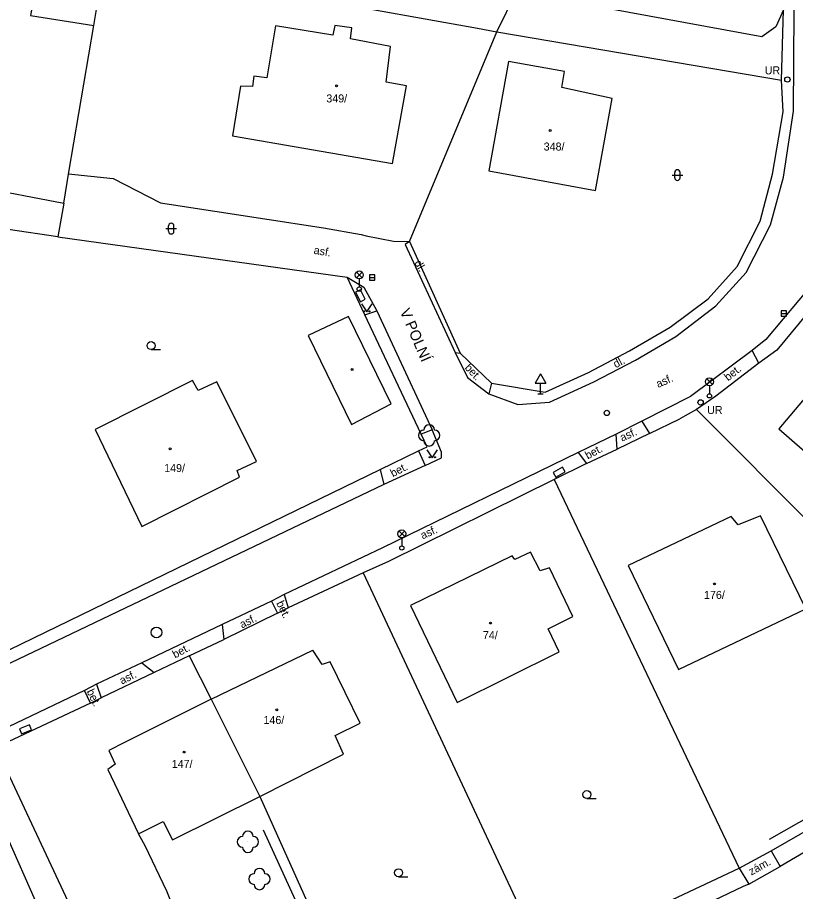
# Model space of a CAD drawing. Extents: x -737812 to -729375, y -1123000 to -1115500.
# Drawn here: x -736746 to -736673, y -1119111.9 to -1119030 of the extents above; entities that cross this region are included whole.
import ezdxf

# ---------------------------------------------------------------- set-up
doc = ezdxf.new("R2010")
doc.units = 0
for name, color, linetype in [('Doplněk polohopisu', 7, 'Continuous'), ('Doplňkové značky', 7, 'Continuous'), ('Hranice - ploty_ zdi', 7, 'Continuous'), ('Hranice parcel a úz_ celk', 7, 'Continuous'), ('Komunikace', 7, 'Continuous'), ('Názvy ulic_ silnic_ žel_', 7, 'Continuous'), ('Pomocné popisy', 7, 'Continuous'), ('Popisy povr_ zn_ inž_ sítí', 7, 'Continuous'), ('Povr_ zn_ inž_ sítí - el_', 7, 'Continuous'), ('Povr_ zn_ inž_ sítí - kan_', 7, 'Continuous'), ('Povr_ zn_ inž_ sítí - vod_', 7, 'Continuous'), ('Stavební objekty', 7, 'Continuous'), ('Zeleň', 7, 'Continuous'), ('Značky druhů budov', 7, 'Continuous'), ('Značky druhů pozemků', 7, 'Continuous'), ('Čísla popisná', 7, 'Continuous')]:
    doc.layers.add(name, color=color, linetype=linetype)

msp = doc.modelspace()

# ---------------------------------------------------------------- linework, layer by layer
at = {"layer": 'Doplněk polohopisu'}
for p, q in [((-736704.94, -1119061.39), (-736704.48, -1119061.44)), ((-736676.47, -1119062.4), (-736677.12, -1119061.2)), ((-736701.54, -1119064.26), (-736701.78, -1119065.25)), ((-736687.44, -1119067.82), (-736686.74, -1119068.98)), ((-736689.75, -1119070.44), (-736689.84, -1119069.05)), ((-736708.4, -1119070.6), (-736707.77, -1119071.98)), ((-736693.41, -1119070.77), (-736692.65, -1119071.8)), ((-736711.99, -1119072.36), (-736711.64, -1119073.76)), ((-736720.99, -1119084.08), (-736720.6, -1119085.33)), ((-736722.18, -1119084.69), (-736721.6, -1119085.82)), ((-736726.78, -1119086.89), (-736726.64, -1119088.27)), ((-736734.33, -1119090.48), (-736733.18, -1119091.39)), ((-736738.59, -1119092.47), (-736738.15, -1119093.74)), ((-736739.13, -1119094.25), (-736739.7, -1119093.05)), ((-736675.33, -1119108.09), (-736674.48, -1119109.57)), ((-736678.31, -1119109.7), (-736677.43, -1119111.21))]:
    msp.add_line(p, q, dxfattribs=at)
msp.add_lwpolyline([(-736728.21, -1119123.67), (-736727.75, -1119122.27), (-736729.05, -1119119.27), (-736731.98, -1119111.87), (-736734.02, -1119107.61), (-736734.63, -1119106.48)], dxfattribs=at)
at = {"layer": 'Doplňkové značky'}
for p, q in [((-736696.94, -1119063.394), (-736697.44, -1119064.26)), ((-736696.94, -1119063.394), (-736696.44, -1119064.26)), ((-736697.44, -1119064.26), (-736696.44, -1119064.26)), ((-736696.94, -1119065.26), (-736696.94, -1119064.26)), ((-736697.19, -1119065.26), (-736696.69, -1119065.26))]:
    msp.add_line(p, q, dxfattribs=at)
at = {"layer": 'Hranice - ploty_ zdi'}
for p, q in [((-736717.3, -1119049.7), (-736713.76, -1119050.33)), ((-736713.76, -1119050.33), (-736713.3, -1119050.46)), ((-736713.3, -1119050.46), (-736710.72, -1119050.95)), ((-736704.48, -1119061.44), (-736701.54, -1119064.26)), ((-736676.47, -1119062.4), (-736680.5, -1119065.47)), ((-736682.31, -1119066.74), (-736653.66, -1119095.54)), ((-736686.74, -1119068.98), (-736683.88, -1119067.59)), ((-736686.74, -1119068.98), (-736689.75, -1119070.44)), ((-736692.65, -1119071.8), (-736689.75, -1119070.44)), ((-736711.99, -1119072.36), (-736708.4, -1119070.6)), ((-736750.09, -1119090.85), (-736711.99, -1119072.36)), ((-736695.67, -1119073.3), (-736678.31, -1119109.7)), ((-736711.19, -1119080.96), (-736713.57, -1119082.02)), ((-736713.57, -1119082.02), (-736720.6, -1119085.33)), ((-736721.6, -1119085.82), (-736726.64, -1119088.27)), ((-736721.6, -1119085.82), (-736720.6, -1119085.33)), ((-736729.89, -1119089.81), (-736726.64, -1119088.27)), ((-736729.89, -1119089.81), (-736733.18, -1119091.39)), ((-736733.18, -1119091.39), (-736738.15, -1119093.74)), ((-736739.13, -1119094.25), (-736738.15, -1119093.74)), ((-736739.13, -1119094.25), (-736748.01, -1119098.42)), ((-736675.33, -1119108.09), (-736653.66, -1119095.54)), ((-736748.01, -1119098.42), (-736730.91, -1119134.89)), ((-736715.82, -1119121.66), (-736722.91, -1119106.16)), ((-736678.31, -1119109.7), (-736675.33, -1119108.09))]:
    msp.add_line(p, q, dxfattribs=at)
for points in [[(-736674.34, -1119035.88), (-736674.17, -1119029.27), (-736674.52, -1119013.55)], [(-736701.54, -1119064.26), (-736696.52, -1119065.09), (-736692.45, -1119063.25), (-736688.59, -1119061.23), (-736684.8, -1119059.01), (-736681.22, -1119056.35), (-736678.52, -1119053.32), (-736676.37, -1119049.09), (-736675.19, -1119044.68), (-736674.21, -1119038.83), (-736674.34, -1119035.88)], [(-736710.72, -1119050.95), (-736709.22, -1119050.99), (-736704.48, -1119061.44)], [(-736708.4, -1119070.6), (-736707.56, -1119070.24), (-736708.14, -1119069.03), (-736713.41, -1119057.85), (-736715.07, -1119054.32)], [(-736669.84, -1119055.2), (-736674.8, -1119061.16), (-736676.47, -1119062.4)], [(-736680.5, -1119065.47), (-736682.31, -1119066.74), (-736683.88, -1119067.59)], [(-736692.65, -1119071.8), (-736695.67, -1119073.3), (-736711.19, -1119080.96)], [(-736713.57, -1119082.02), (-736696.6, -1119118.31), (-736678.31, -1119109.7)], [(-736675.48, -1119106.99), (-736662.16, -1119099.43), (-736654.8, -1119095.19)]]:
    msp.add_lwpolyline(points, dxfattribs=at)
at = {"layer": 'Hranice parcel a úz_ celk'}
for points in [[(-736721.98, -1119027.65), (-736717.56, -1119028.37), (-736702.85, -1119031), (-736701.03, -1119031.35), (-736699.21, -1119027.54), (-736694.87, -1119000.96)], [(-736762.16, -1119020.65), (-736762.75, -1119023.57), (-736766.15, -1119042.71), (-736741.65, -1119047.38), (-736741.17, -1119044.5), (-736738.81, -1119030.75)], [(-736674.17, -1119029.27), (-736674.89, -1119030.86), (-736676.21, -1119031.8), (-736699.21, -1119027.54)], [(-736709.22, -1119050.99), (-736701.03, -1119031.35)], [(-736701.03, -1119031.35), (-736674.34, -1119035.88)], [(-736741.2, -1119044.64), (-736737.02, -1119045.09), (-736732.59, -1119047.35), (-736717.3, -1119049.7)], [(-736741.65, -1119047.38), (-736742.19, -1119050.56)], [(-736742.19, -1119050.56), (-736746.85, -1119049.85), (-736749.66, -1119065.55), (-736753.25, -1119085.33), (-736750.09, -1119090.85)], [(-736742.19, -1119050.56), (-736715.07, -1119054.32)], [(-736729.89, -1119089.81), (-736727.81, -1119093.86)], [(-736723.27, -1119103.01), (-736712.86, -1119126.14)]]:
    msp.add_lwpolyline(points, dxfattribs=at)
at = {"layer": 'Komunikace'}
for p, q in [((-736706.23, -1119070.74), (-736707.09, -1119068.62)), ((-736677.43, -1119111.21), (-736674.48, -1119109.57))]:
    msp.add_line(p, q, dxfattribs=at)
for points in [[(-736709.22, -1119050.99), (-736709.63, -1119051.26), (-736704.94, -1119061.39), (-736703.79, -1119063.73), (-736701.78, -1119065.25), (-736699.06, -1119066.27), (-736696.09, -1119066.04), (-736691.94, -1119064.15), (-736688.04, -1119062.12), (-736684.26, -1119059.88), (-736680.51, -1119057.01), (-736677.68, -1119053.89), (-736675.4, -1119049.41), (-736674.17, -1119044.97), (-736673.23, -1119038.76), (-736673.18, -1119029.34), (-736673.35, -1119014.3), (-736673.44, -1119007.2), (-736673.57, -1118998.78)], [(-736622.49, -1119039.69), (-736623.12, -1119051.94), (-736624.1, -1119057.97), (-736625.9, -1119062.7), (-736628.62, -1119067), (-736631.54, -1119071), (-736641.44, -1119083.19), (-736650.2, -1119093.89), (-736652.55, -1119096.41), (-736657.99, -1119099.87), (-736674.48, -1119109.57)], [(-736671.1, -1119054.56), (-736675.81, -1119060.17), (-736677.12, -1119061.2), (-736682.9, -1119065.51), (-736687.44, -1119067.82), (-736689.84, -1119069.05), (-736693.41, -1119070.77), (-736711.76, -1119079.68), (-736720.99, -1119084.08), (-736722.18, -1119084.69), (-736726.78, -1119086.89), (-736734.33, -1119090.48), (-736738.59, -1119092.47), (-736739.7, -1119093.05), (-736762.61, -1119103.99), (-736767.67, -1119106.4), (-736771.32, -1119108.21)], [(-736715.07, -1119054.32), (-736713.51, -1119055.25), (-736712.28, -1119057.48)], [(-736707.77, -1119071.98), (-736706.24, -1119071.25), (-736706.23, -1119070.74)], [(-736707.77, -1119071.98), (-736711.64, -1119073.76), (-736749.52, -1119091.84), (-736775.93, -1119104.4), (-736780.5, -1119106.57), (-736783.56, -1119108)], [(-736677.43, -1119111.21), (-736677.95, -1119111.44), (-736724.57, -1119133.68)]]:
    msp.add_lwpolyline(points, dxfattribs=at)
at = {"layer": 'Povr_ zn_ inž_ sítí - el_'}
for p, q in [((-736714.204, -1119054.378), (-736713.676, -1119053.85)), ((-736713.668, -1119054.375), (-736714.196, -1119053.846)), ((-736713.94, -1119054.49), (-736713.94, -1119055.24)), ((-736681.374, -1119064.388), (-736680.846, -1119063.86)), ((-736680.838, -1119064.385), (-736681.366, -1119063.856)), ((-736681.11, -1119064.5), (-736681.11, -1119065.25)), ((-736710.214, -1119078.648), (-736709.686, -1119078.12)), ((-736709.678, -1119078.645), (-736710.206, -1119078.116)), ((-736709.95, -1119078.76), (-736709.95, -1119079.51))]:
    msp.add_line(p, q, dxfattribs=at)
for points in [[(-736714.281, -1119055.74), (-736713.824, -1119056.629), (-736713.379, -1119056.4), (-736713.836, -1119055.511)], [(-736695.516, -1119073.061), (-736694.641, -1119072.576), (-736694.884, -1119072.139), (-736695.759, -1119072.624)], [(-736745.599, -1119097.13), (-736744.673, -1119096.753), (-736744.861, -1119096.29), (-736745.787, -1119096.667)]]:
    msp.add_lwpolyline(points, close=True, dxfattribs=at)
for centre, radius in [((-736673.801, -1119035.8), 0.25), ((-736673.801, -1119035.8), 0.0005), ((-736713.94, -1119054.115), 0.375), ((-736713.94, -1119055.44), 0.2), ((-736681.11, -1119064.125), 0.375), ((-736681.11, -1119065.45), 0.2), ((-736681.941, -1119066.06), 0.25), ((-736681.941, -1119066.06), 0.0005), ((-736709.95, -1119078.385), 0.375), ((-736709.95, -1119079.71), 0.2)]:
    msp.add_circle(centre, radius, dxfattribs=at)
at = {"layer": 'Povr_ zn_ inž_ sítí - kan_'}
for p, q in [((-736712.99, -1119054.36), (-736712.49, -1119054.36)), ((-736674.39, -1119057.74), (-736673.89, -1119057.74))]:
    msp.add_line(p, q, dxfattribs=at)
for points in [[(-736712.99, -1119054.611), (-736712.49, -1119054.611), (-736712.49, -1119054.11), (-736712.99, -1119054.11)], [(-736674.39, -1119057.991), (-736673.89, -1119057.991), (-736673.89, -1119057.49), (-736674.39, -1119057.49)]]:
    msp.add_lwpolyline(points, close=True, dxfattribs=at)
msp.add_circle((-736732.95, -1119087.62), 0.5, dxfattribs=at)
at = {"layer": 'Povr_ zn_ inž_ sítí - vod_'}
msp.add_circle((-736690.73, -1119067.05), 0.25, dxfattribs=at)
at = {"layer": 'Stavební objekty'}
for points in [[(-736743.77, -1119024.28), (-736744.76, -1119029.81), (-736738.81, -1119030.75), (-736737.91, -1119025.27)], [(-736725.84, -1119041.09), (-736710.81, -1119043.67), (-736709.52, -1119036.39), (-736711.41, -1119036.04), (-736711.02, -1119032.72), (-736714.77, -1119031.99), (-736714.64, -1119030.96), (-736716.24, -1119030.74), (-736716.41, -1119031.65), (-736721.79, -1119030.78), (-736722.61, -1119035.65), (-736723.82, -1119035.48), (-736723.95, -1119036.47), (-736725.07, -1119036.43)], [(-736699.94, -1119034.12), (-736701.78, -1119044.37), (-736691.78, -1119046.21), (-736690.22, -1119037.58), (-736694.94, -1119036.54), (-736694.71, -1119035.04)], [(-736694.71, -1119035.04), (-736699.94, -1119034.12)], [(-736725.07, -1119036.43), (-736725.84, -1119041.09)], [(-736718.72, -1119059.8), (-736714.67, -1119068.13), (-736710.94, -1119066.19), (-736714.94, -1119058.01)], [(-736714.94, -1119058.01), (-736718.72, -1119059.8)], [(-736667.26, -1119059.85), (-736674.59, -1119068.54), (-736667.07, -1119075.09), (-736659.65, -1119066.4), (-736658.3, -1119064.82), (-736664.85, -1119059.3), (-736666.1, -1119060.78)], [(-736725.39, -1119072.46), (-736723.58, -1119071.6), (-736727.3, -1119064.15), (-736729.04, -1119064.94), (-736729.56, -1119064.02), (-736738.71, -1119068.6)], [(-736738.71, -1119068.6), (-736734.34, -1119077.69), (-736725.18, -1119073.07), (-736725.39, -1119072.46)], [(-736679.06, -1119076.76), (-736688.72, -1119081.35), (-736684.02, -1119091.09), (-736672.06, -1119085.41), (-736676.33, -1119076.69), (-736678.42, -1119077.55)], [(-736678.42, -1119077.55), (-736679.06, -1119076.76)], [(-736709.13, -1119085.09), (-736704.76, -1119094.2), (-736695.19, -1119089.43), (-736696.23, -1119087.28), (-736693.93, -1119086.13), (-736696.12, -1119081.57), (-736696.98, -1119081.86), (-736697.88, -1119080.1), (-736699.34, -1119080.79), (-736699.6, -1119080.43)], [(-736699.6, -1119080.43), (-736709.13, -1119085.09)], [(-736727.81, -1119093.86), (-736723.27, -1119103.01), (-736715.41, -1119099.04), (-736716.2, -1119097.29), (-736713.87, -1119096.11), (-736716.66, -1119090.36), (-736717.41, -1119090.64), (-736718.3, -1119089.29)], [(-736727.81, -1119093.86), (-736718.3, -1119089.29)], [(-736727.81, -1119093.86), (-736735.95, -1119097.94), (-736737.41, -1119098.69), (-736736.84, -1119099.97), (-736737.52, -1119100.47), (-736734.63, -1119106.48), (-736732.34, -1119105.33), (-736731.45, -1119107.05), (-736723.27, -1119103.01)], [(-736748, -1119104.47), (-736743.27, -1119115.16), (-736750.39, -1119118.54), (-736749.63, -1119119.94), (-736755.7, -1119122.69), (-736760.61, -1119111.65), (-736756.75, -1119109.61), (-736757.22, -1119108.26), (-736755.64, -1119107.74), (-736755.29, -1119108.26), (-736753.43, -1119107.27), (-736753.72, -1119106.75)]]:
    msp.add_lwpolyline(points, dxfattribs=at)
at = {"layer": 'Zeleň'}
msp.add_lwpolyline([(-736713.41, -1119057.85), (-736712.28, -1119057.48), (-736707.09, -1119068.62), (-736708.14, -1119069.03)], dxfattribs=at)
for centre in [(-736707.39, -1119069.15), (-736724.38, -1119107.24), (-736723.3, -1119110.73)]:
    msp.add_circle(centre, 0.0005, dxfattribs=at)
for centre, start, end in [((-736707.89, -1119069.15), 89.99999, 269.99999), ((-736707.39, -1119068.65), 0, 179.99999), ((-736706.89, -1119069.15), 270, 89.99999), ((-736707.39, -1119069.65), 179.99999, 359.99999), ((-736724.38, -1119106.74), 0, 179.99999), ((-736724.88, -1119107.24), 89.99999, 269.99999), ((-736723.88, -1119107.24), 270, 89.99999), ((-736724.38, -1119107.74), 179.99999, 359.99999), ((-736723.3, -1119110.23), 0, 179.99999), ((-736723.8, -1119110.73), 89.99999, 269.99999), ((-736722.8, -1119110.73), 270, 89.99999), ((-736723.3, -1119111.23), 179.99999, 359.99999)]:
    msp.add_arc(centre, 0.5, start, end, dxfattribs=at)
at = {"layer": 'Značky druhů budov'}
for centre in [(-736716.06, -1119036.4), (-736696.04, -1119040.58), (-736714.62, -1119062.98), (-736731.67, -1119070.42), (-736680.64, -1119083.08), (-736701.64, -1119086.74), (-736721.68, -1119094.88), (-736730.36, -1119098.83)]:
    msp.add_circle(centre, 0.0875, dxfattribs=at)
at = {"layer": 'Značky druhů pozemků'}
for p, q in [((-736684.62, -1119044.76), (-736683.62, -1119044.76)), ((-736684.37, -1119045.01), (-736684.37, -1119044.51)), ((-736683.87, -1119045.01), (-736683.87, -1119044.51)), ((-736732.07, -1119049.78), (-736731.07, -1119049.78)), ((-736731.82, -1119050.03), (-736731.82, -1119049.53)), ((-736731.32, -1119050.03), (-736731.32, -1119049.53)), ((-736733.46, -1119061.115), (-736732.585, -1119061.115)), ((-736692.6, -1119103.185), (-736691.725, -1119103.185)), ((-736710.26, -1119110.515), (-736709.385, -1119110.515))]:
    msp.add_line(p, q, dxfattribs=at)
for points in [[(-736713.74, -1119056.83), (-736713.24, -1119057.58), (-736712.74, -1119056.83)], [(-736707.59, -1119070.5), (-736707.09, -1119071.25), (-736706.59, -1119070.5)]]:
    msp.add_lwpolyline(points, dxfattribs=at)
for centre, radius in [((-736713.49, -1119057.53), 0.05), ((-736712.99, -1119057.53), 0.05), ((-736733.46, -1119060.74), 0.375), ((-736707.34, -1119071.2), 0.05), ((-736706.84, -1119071.2), 0.05), ((-736692.6, -1119102.81), 0.375), ((-736710.26, -1119110.14), 0.375)]:
    msp.add_circle(centre, radius, dxfattribs=at)
for centre, start, end in [((-736684.12, -1119044.51), 0, 179.99999), ((-736684.12, -1119045.01), 179.99999, 359.99999), ((-736731.57, -1119049.53), 0, 179.99999), ((-736731.57, -1119050.03), 179.99999, 359.99999)]:
    msp.add_arc(centre, 0.25, start, end, dxfattribs=at)

# ---------------------------------------------------------------- texts
at = {"layer": 'Názvy ulic_ silnic_ žel_'}
msp.add_text('V POLNÍ', height=1, rotation=293.27086, dxfattribs=at).set_placement((-736710.16, -1119057.52))
at = {"layer": 'Pomocné popisy'}
for s, rotation, p in [('asf.', 350.48489, (-736718.25, -1119052.13)), ('dl.', 299.46363, (-736708.8, -1119052.98)), ('dl.', 28.07249, (-736689.89, -1119062.87)), ('bet.', 313.19471, (-736704.11, -1119062.86)), ('bet.', 38.73868, (-736679.36, -1119064.1)), ('asf.', 24.44396, (-736685.91, -1119064.72)), ('asf.', 24.44396, (-736689.3, -1119069.75)), ('bet.', 28.57275, (-736692.52, -1119071.42)), ('bet.', 27.56357, (-736710.79, -1119073.09)), ('asf.', 24.44396, (-736708, -1119078.91)), ('bet.', 295.80693, (-736721.74, -1119084.87)), ('asf.', 26.56505, (-736724.93, -1119087.26)), ('bet.', 28.23069, (-736731.21, -1119090.07)), ('asf.', 26.56505, (-736736.19, -1119092.52)), ('bet.', 295.80693, (-736739.52, -1119093.14)), ('zám.', 29.07109, (-736677.18, -1119110.41))]:
    msp.add_text(s, height=0.75, rotation=rotation, dxfattribs=at).set_placement(p)
at = {"layer": 'Popisy povr_ zn_ inž_ sítí'}
for p in [(-736675.93, -1119035.32), (-736681.33, -1119067.15)]:
    msp.add_text('UR', height=0.75, dxfattribs=at).set_placement(p)
at = {"layer": 'Čísla popisná'}
for s, p in [('349/', (-736717.03, -1119037.95)), ('348/', (-736696.65, -1119042.46)), ('149/', (-736732.23, -1119072.59)), ('176/', (-736681.62, -1119084.48)), ('74/', (-736702.35, -1119088.25)), ('146/', (-736722.92, -1119096.2)), ('147/', (-736731.52, -1119100.32))]:
    msp.add_text(s, height=0.75, dxfattribs=at).set_placement(p)

doc.saveas('drawing.dxf')
